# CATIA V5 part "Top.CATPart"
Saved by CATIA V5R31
Part number: Part1.1
Bounding box of the stored display mesh (mm): x -50 to 50, y -25 to 25, z -20 to 0
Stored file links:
  D:\PROJECTS\Project 2021\US EDITION\CATIA V5 6R 2021\Resources\Part Files\c12_catia_v5_6r2021_prt\c12_catia_v5-6r2021 figr_12-8\Top.CATPart
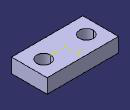
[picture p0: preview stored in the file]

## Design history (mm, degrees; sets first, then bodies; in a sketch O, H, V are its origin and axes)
Body1 (main body)
  Sketch1 on xy-plane, origin (0, 0, 0), H (1, 0, 0), V (0, 1, 0)
    line L1 (50, 25) -> (50, -25)
    line L2 (50, -25) -> (-50, -25)
    line L3 (-50, -25) -> (-50, 25)
    line L4 (-50, 25) -> (50, 25)
    circle A1 centre (-30, 0) radius 10
    point P5 (-30, 0)
    circle A2 centre (30, 0) radius 10
    length L2 = 100
    length L1 = 50
    radius A1 = 10
    distance P5 V = 30
    vertical: L1 V, L3 V
    horizontal: L2 H, L4 H
    equidistance: L1 L3 O, L2 L4 O
    coincidence: P5 H
    symmetry: A1 A2 V
  Pad1: profile Sketch1, direction (0, 0, -1), length 20
  Sketch2 on face of Pad1, origin (0, 0, 0), H (1, 0, 0), V (0, 1, 0)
